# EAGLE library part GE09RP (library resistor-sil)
SIL RESISTOR
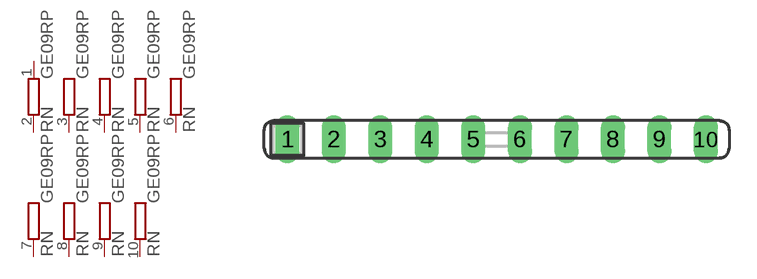
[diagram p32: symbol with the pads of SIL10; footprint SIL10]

Designator prefix RN; gates A=R-PV B=R-PV1 C=R-PV1 D=R-PV1 E=R-PV1 F=R-PV1 G=R-PV1 H=R-PV1 I=R-PV1

## GE09RP (OC_FARNELL: unknown; OC_NEWARK: unknown)  [SIL10]
1  A:1  pas
2  A:2  pas
3  B:2  pas
4  C:2  pas
5  D:2  pas
6  E:2  pas
7  F:2  pas
8  G:2  pas
9  H:2  pas
10  I:2  pas

## Footprint SIL10 (pad centres in mm)
Single In Line
drill 0.813 long: 1 -11.43,0; 2 -8.89,0; 3 -6.35,0; 4 -3.81,0; 5 -1.27,0; 6 1.27,0; 7 3.81,0; 8 6.35,0; 9 8.89,0; 10 11.43,0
